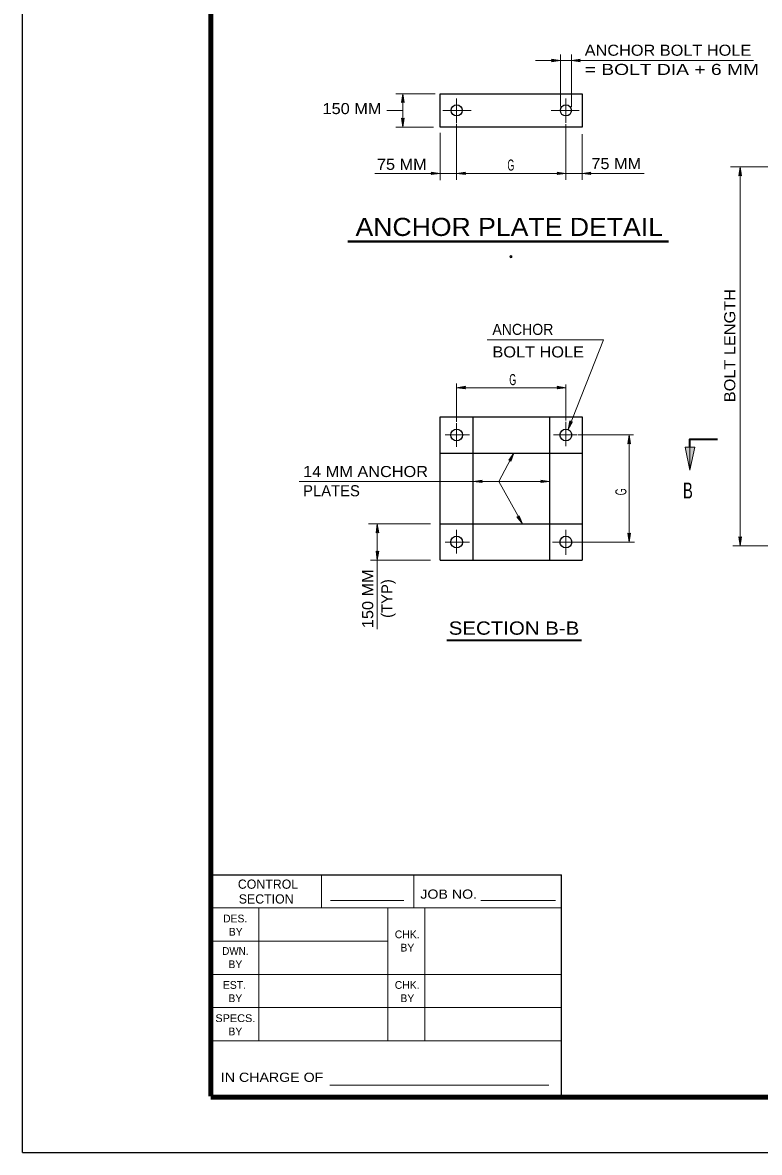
# Model space of a CAD drawing. Extents: x 312601.859 to 312602.7, y 144420.109 to 144420.704.
# Drawn here: x 312601.8593 to 312602.0589, y 144420.1095 to 144420.4155 of the extents above; entities that cross this region are included whole.
import ezdxf
from ezdxf.enums import TextEntityAlignment as Align

# ---------------------------------------------------------------- set-up
doc = ezdxf.new("R2010")
doc.units = 0
doc.header["$LTSCALE"] = 0.0012
doc.header["$PDMODE"] = 32
doc.header["$PDSIZE"] = 0.0006
doc.linetypes.add('DOT_DASHED', pattern=[7.7, 5, -1.2, 0.3, -1.2])
doc.linetypes.add('LONG_DASHED', pattern=[7.5, 6, -1.5])
for name, color, linetype, lineweight in [('1', 7, 'Continuous', 13), ('2', 7, 'Continuous', 13), ('39', 7, 'Continuous', 13)]:
    doc.layers.add(name, color=color, linetype=linetype, lineweight=lineweight)

msp = doc.modelspace()

# ---------------------------------------------------------------- hatches: boundary and pattern name
at = {"layer": '1'}
for points in [[(312602.0388, 144420.3005), (312602.0401, 144420.3005), (312602.0401, 144420.2943)], [(312602.0414, 144420.3005), (312602.0401, 144420.3005), (312602.0401, 144420.2943)]]:
    msp.add_hatch(color=256, dxfattribs=at).paths.add_polyline_path(points)
at = {"layer": '39'}
for points in [[(312602.0028, 144420.4052), (312602.0026, 144420.4056), (312602.005, 144420.4052), (312602.0026, 144420.4049)], [(312602.0102, 144420.4052), (312602.0104, 144420.4049), (312602.008, 144420.4052), (312602.0104, 144420.4056)], [(312601.9623, 144420.394), (312601.962, 144420.3938), (312601.9623, 144420.3962), (312601.9627, 144420.3938)], [(312601.9623, 144420.3894), (312601.9627, 144420.3896), (312601.9623, 144420.3872), (312601.962, 144420.3896)], [(312602.0537, 144420.3742), (312602.0534, 144420.374), (312602.0537, 144420.3764), (312602.0541, 144420.374)], [(312601.9702, 144420.3746), (312601.97, 144420.375), (312601.9724, 144420.3746), (312601.97, 144420.3743)], [(312601.9791, 144420.3746), (312601.9793, 144420.3743), (312601.9769, 144420.3746), (312601.9793, 144420.375)], [(312602.0043, 144420.3746), (312602.0041, 144420.375), (312602.0065, 144420.3746), (312602.0041, 144420.3743)], [(312602.0131, 144420.3746), (312602.0133, 144420.3743), (312602.0109, 144420.3746), (312602.0133, 144420.375)], [(312601.9791, 144420.3166), (312601.9793, 144420.3163), (312601.9769, 144420.3166), (312601.9793, 144420.317)], [(312602.0043, 144420.3166), (312602.0041, 144420.317), (312602.0065, 144420.3166), (312602.0041, 144420.3163)], [(312602.0079, 144420.3073), (312602.0083, 144420.3074), (312602.0071, 144420.3053), (312602.0076, 144420.3076)], [(312602.0236, 144420.3016), (312602.0233, 144420.3014), (312602.0236, 144420.3038), (312602.024, 144420.3014)], [(312601.9914, 144420.297), (312601.991, 144420.297), (312601.9924, 144420.2989), (312601.9916, 144420.2966)], [(312601.9836, 144420.2912), (312601.9838, 144420.2909), (312601.9814, 144420.2912), (312601.9838, 144420.2916)], [(312601.9999, 144420.2912), (312601.9997, 144420.2916), (312602.0021, 144420.2912), (312601.9997, 144420.2909)], [(312601.9936, 144420.2816), (312601.9938, 144420.2819), (312601.9947, 144420.2797), (312601.9932, 144420.2816)], [(312601.9554, 144420.2775), (312601.9551, 144420.2773), (312601.9554, 144420.2797), (312601.9558, 144420.2773)], [(312602.0236, 144420.277), (312602.024, 144420.2772), (312602.0236, 144420.2748), (312602.0233, 144420.2772)], [(312602.0537, 144420.276), (312602.0541, 144420.2762), (312602.0537, 144420.2738), (312602.0534, 144420.2762)], [(312601.9554, 144420.2721), (312601.9558, 144420.2723), (312601.9554, 144420.2699), (312601.9551, 144420.2723)]]:
    msp.add_hatch(color=256, dxfattribs=at).paths.add_polyline_path(points)

# ---------------------------------------------------------------- linework, layer by layer
at = {"layer": '1'}
for p, q in [((312602.005, 144420.4068), (312602.005, 144420.3928)), ((312602.008, 144420.4068), (312602.008, 144420.3927)), ((312601.9604, 144420.3962), (312601.9711, 144420.3962)), ((312601.9769, 144420.3881), (312601.9769, 144420.3729)), ((312602.0065, 144420.388), (312602.0065, 144420.3729)), ((312601.9706, 144420.3872), (312601.9604, 144420.3872)), ((312601.9623, 144420.3872), (312601.9623, 144420.3871)), ((312601.9724, 144420.3728), (312601.9724, 144420.3856)), ((312602.0109, 144420.3853), (312602.0109, 144420.3729)), ((312602.0511, 144420.3764), (312602.1223, 144420.3764)), ((312602.0537, 144420.3764), (312602.0537, 144420.2738)), ((312601.9547, 144420.3746), (312601.9724, 144420.3746)), ((312601.9724, 144420.3746), (312601.9769, 144420.3746)), ((312602.0109, 144420.3746), (312602.0277, 144420.3746)), ((312601.9852, 144420.3296), (312602.0167, 144420.3296)), ((312602.0071, 144420.3053), (312602.0167, 144420.3296)), ((312601.9769, 144420.3177), (312601.9769, 144420.3074)), ((312602.0065, 144420.3175), (312602.0065, 144420.3077)), ((312601.9769, 144420.3166), (312602.0065, 144420.3166)), ((312602.0097, 144420.3038), (312602.0248, 144420.3038)), ((312602.0236, 144420.3038), (312602.0236, 144420.2748)), ((312601.9883, 144420.2912), (312601.9924, 144420.2989)), ((312601.9883, 144420.2912), (312601.9947, 144420.2797)), ((312601.953, 144420.2797), (312601.9698, 144420.2797)), ((312602.0251, 144420.2748), (312602.0084, 144420.2748)), ((312602.0517, 144420.2738), (312602.1215, 144420.2738)), ((312601.9536, 144420.2699), (312601.9698, 144420.2699))]:
    msp.add_line(p, q, dxfattribs=at)
at = {"layer": '1', "lineweight": 25}
for p, q in [((312601.9724, 144420.3872), (312601.9724, 144420.3962)), ((312601.9724, 144420.3962), (312602.0109, 144420.3962)), ((312602.0109, 144420.3962), (312602.0109, 144420.3872)), ((312602.0109, 144420.3872), (312601.9724, 144420.3872)), ((312601.9724, 144420.3087), (312602.0109, 144420.3087)), ((312601.9724, 144420.2699), (312601.9724, 144420.3087)), ((312602.011, 144420.2699), (312602.011, 144420.3087)), ((312601.9814, 144420.2797), (312601.9814, 144420.2989)), ((312602.0021, 144420.2989), (312602.0021, 144420.2797)), ((312601.9724, 144420.2699), (312602.0109, 144420.2699))]:
    msp.add_line(p, q, dxfattribs=at)
at = {"layer": '1', "linetype": 'DOT_DASHED'}
for p, q in [((312601.9769, 144420.3949), (312601.9769, 144420.3883)), ((312602.0065, 144420.3949), (312602.0065, 144420.3883)), ((312601.9732, 144420.3917), (312601.9808, 144420.3917)), ((312602.0025, 144420.3917), (312602.0101, 144420.3917)), ((312601.9769, 144420.307), (312601.9769, 144420.3006)), ((312602.0065, 144420.3074), (312602.0065, 144420.3008)), ((312601.9738, 144420.3038), (312601.9804, 144420.3038)), ((312602.0031, 144420.3038), (312602.0095, 144420.3038)), ((312601.9769, 144420.2781), (312601.9769, 144420.2717)), ((312602.0065, 144420.2781), (312602.0065, 144420.2713)), ((312601.9738, 144420.2748), (312601.9804, 144420.2748)), ((312602.0029, 144420.2748), (312602.0099, 144420.2748))]:
    msp.add_line(p, q, dxfattribs=at)
at = {"layer": '1', "linetype": 'LONG_DASHED', "lineweight": 25}
for p, q in [((312601.9814, 144420.2989), (312601.9814, 144420.3087)), ((312602.0021, 144420.3087), (312602.0021, 144420.2989)), ((312601.9814, 144420.2699), (312601.9814, 144420.2797)), ((312602.0021, 144420.2797), (312602.0021, 144420.2699))]:
    msp.add_line(p, q, dxfattribs=at)
at = {"layer": '1'}
for points in [[(312601.9983, 144420.4052), (312602.005, 144420.4052), (312602.008, 144420.4052), (312602.0573, 144420.4052)], [(312601.9623, 144420.3963), (312601.9623, 144420.3962), (312601.9623, 144420.3872)], [(312601.9769, 144420.3746), (312602.0065, 144420.3746), (312602.0109, 144420.3746)], [(312601.9342, 144420.2912), (312601.9814, 144420.2912), (312602.0021, 144420.2912)], [(312601.9554, 144420.2797), (312601.9554, 144420.2699), (312601.9554, 144420.2512)]]:
    msp.add_lwpolyline(points, dxfattribs=at)
at = {"layer": '1', "lineweight": 35}
msp.add_lwpolyline([(312602.0401, 144420.3005), (312602.0401, 144420.3027), (312602.0476, 144420.3027)], dxfattribs=at)
at = {"layer": '1', "lineweight": 25}
for points in [[(312601.9724, 144420.2989), (312601.9814, 144420.2989), (312602.0021, 144420.2989), (312602.0109, 144420.2989)], [(312601.9724, 144420.2797), (312601.9814, 144420.2797), (312602.0021, 144420.2797), (312602.0109, 144420.2797)]]:
    msp.add_lwpolyline(points, dxfattribs=at)
at = {"layer": '1'}
for points in [[(312602.0388, 144420.3005), (312602.0401, 144420.3005), (312602.0401, 144420.2943)], [(312602.0414, 144420.3005), (312602.0401, 144420.3005), (312602.0401, 144420.2943)]]:
    msp.add_lwpolyline(points, close=True, dxfattribs=at)
at = {"layer": '1', "lineweight": 25}
for centre, radius in [((312601.9769, 144420.3917), 0.0015), ((312602.0065, 144420.3917), 0.0015), ((312601.9769, 144420.3038), 0.0016), ((312602.0065, 144420.3038), 0.0016), ((312601.9769, 144420.2748), 0.0016), ((312602.0065, 144420.2748), 0.0016)]:
    msp.add_circle(centre, radius, dxfattribs=at)
at = {"layer": '2'}
msp.add_line((312601.9623, 144420.3917), (312601.958, 144420.3917), dxfattribs=at)
at = {"layer": '2', "lineweight": 40}
msp.add_line((312602.0343, 144420.3562), (312601.9474, 144420.3562), dxfattribs=at)
at = {"layer": '2', "lineweight": 35}
msp.add_line((312601.9742, 144420.2482), (312602.0107, 144420.2482), dxfattribs=at)
at = {"layer": '2'}
msp.add_point((312601.9916, 144420.3521), dxfattribs=at)
at = {"layer": '39', "lineweight": 25}
for p, q in [((312601.8593, 144420.1095), (312601.8593, 144420.7035)), ((312601.9103, 144420.1847), (312602.0053, 144420.1847)), ((312602.0053, 144420.1247), (312602.0053, 144420.1847))]:
    msp.add_line(p, q, dxfattribs=at)
at = {"layer": '39'}
for p, q in [((312601.9103, 144420.1247), (312601.9103, 144420.1847)), ((312601.9403, 144420.1757), (312601.9403, 144420.1847)), ((312601.9653, 144420.1757), (312601.9653, 144420.1847)), ((312601.9427, 144420.1777), (312601.9626, 144420.1777)), ((312601.9835, 144420.1777), (312602.0037, 144420.1777)), ((312601.9103, 144420.1757), (312602.0053, 144420.1757)), ((312601.9233, 144420.1397), (312601.9233, 144420.1757)), ((312601.9583, 144420.1397), (312601.9583, 144420.1757)), ((312601.9683, 144420.1397), (312601.9683, 144420.1757)), ((312601.9103, 144420.1667), (312601.9583, 144420.1667)), ((312601.9103, 144420.1577), (312602.0053, 144420.1577)), ((312601.9103, 144420.1487), (312602.0053, 144420.1487)), ((312601.9103, 144420.1397), (312602.0053, 144420.1397)), ((312601.9425, 144420.1277), (312602.0019, 144420.1277)), ((312601.9103, 144420.1247), (312602.0053, 144420.1247))]:
    msp.add_line(p, q, dxfattribs=at)
at = {"layer": '39', "lineweight": 25}
msp.add_lwpolyline([(312601.8593, 144420.1095), (312602.7003, 144420.1095), (312602.7003, 144420.7035)], dxfattribs=at)
at = {"layer": '39', "lineweight": 158}
for points in [[(312601.9103, 144420.1245), (312602.6853, 144420.1245), (312602.6853, 144420.6645)], [(312601.9103, 144420.1247), (312601.9103, 144420.6645), (312602.6853, 144420.6645)]]:
    msp.add_lwpolyline(points, dxfattribs=at)
at = {"layer": '39'}
for points in [[(312602.0028, 144420.4052), (312602.0026, 144420.4056), (312602.005, 144420.4052), (312602.0026, 144420.4049)], [(312602.0102, 144420.4052), (312602.0104, 144420.4049), (312602.008, 144420.4052), (312602.0104, 144420.4056)], [(312601.9623, 144420.394), (312601.962, 144420.3938), (312601.9623, 144420.3962), (312601.9627, 144420.3938)], [(312601.9623, 144420.3894), (312601.9627, 144420.3896), (312601.9623, 144420.3872), (312601.962, 144420.3896)], [(312602.0537, 144420.3742), (312602.0534, 144420.374), (312602.0537, 144420.3764), (312602.0541, 144420.374)], [(312601.9702, 144420.3746), (312601.97, 144420.375), (312601.9724, 144420.3746), (312601.97, 144420.3743)], [(312601.9791, 144420.3746), (312601.9793, 144420.3743), (312601.9769, 144420.3746), (312601.9793, 144420.375)], [(312602.0043, 144420.3746), (312602.0041, 144420.375), (312602.0065, 144420.3746), (312602.0041, 144420.3743)], [(312602.0131, 144420.3746), (312602.0133, 144420.3743), (312602.0109, 144420.3746), (312602.0133, 144420.375)], [(312601.9791, 144420.3166), (312601.9793, 144420.3163), (312601.9769, 144420.3166), (312601.9793, 144420.317)], [(312602.0043, 144420.3166), (312602.0041, 144420.317), (312602.0065, 144420.3166), (312602.0041, 144420.3163)], [(312602.0079, 144420.3073), (312602.0083, 144420.3074), (312602.0071, 144420.3053), (312602.0076, 144420.3076)], [(312602.0236, 144420.3016), (312602.0233, 144420.3014), (312602.0236, 144420.3038), (312602.024, 144420.3014)], [(312601.9914, 144420.297), (312601.991, 144420.297), (312601.9924, 144420.2989), (312601.9916, 144420.2966)], [(312601.9836, 144420.2912), (312601.9838, 144420.2909), (312601.9814, 144420.2912), (312601.9838, 144420.2916)], [(312601.9999, 144420.2912), (312601.9997, 144420.2916), (312602.0021, 144420.2912), (312601.9997, 144420.2909)], [(312601.9936, 144420.2816), (312601.9938, 144420.2819), (312601.9947, 144420.2797), (312601.9932, 144420.2816)], [(312601.9554, 144420.2775), (312601.9551, 144420.2773), (312601.9554, 144420.2797), (312601.9558, 144420.2773)], [(312602.0236, 144420.277), (312602.024, 144420.2772), (312602.0236, 144420.2748), (312602.0233, 144420.2772)], [(312602.0537, 144420.276), (312602.0541, 144420.2762), (312602.0537, 144420.2738), (312602.0534, 144420.2762)], [(312601.9554, 144420.2721), (312601.9558, 144420.2723), (312601.9554, 144420.2699), (312601.9551, 144420.2723)]]:
    msp.add_lwpolyline(points, close=True, dxfattribs=at)

# ---------------------------------------------------------------- texts
at = {"layer": '1'}
for s, height, p in [('CONTROL', 0.0025, (312601.9258, 144420.1809)), ('SECTION', 0.0025, (312601.9253, 144420.1769)), ('DES.', 0.0021, (312601.9169, 144420.1718)), ('BY', 0.0021, (312601.91705, 144420.1682)), ('CHK.', 0.0021, (312601.9635, 144420.1675)), ('BY', 0.0021, (312601.96355, 144420.1639)), ('BY', 0.0021, (312601.91695, 144420.1594)), ('EST.', 0.0021, (312601.9167, 144420.1538)), ('CHK.', 0.0021, (312601.9635, 144420.1538)), ('BY', 0.0021, (312601.91695, 144420.1502)), ('BY', 0.0021, (312601.96355, 144420.1502)), ('BY', 0.0021, (312601.91695, 144420.1412))]:
    msp.add_text(s, height=height, dxfattribs=at).set_placement(p, align=Align.CENTER)
for s, height, width, p in [('JOB NO.', 0.0025, 1.15, (312601.97475, 144420.1782)), ('DWN.', 0.0021, 0.95, (312601.91695, 144420.163)), ('SPECS.', 0.0021, 1.05, (312601.91695, 144420.1448)), ('IN CHARGE OF', 0.0025, 1.15, (312601.9269, 144420.1286))]:
    msp.add_text(s, height=height, dxfattribs=dict(at, width=width)).set_placement(p, align=Align.CENTER)
at = {"layer": '2'}
for s, width, p in [('ANCHOR BOLT HOLE', 1.1, (312602.0116, 144420.4065)), ('= BOLT DIA + 6 MM', 1.3, (312602.0116, 144420.4013)), ('14 MM ANCHOR', 1.1, (312601.9353, 144420.2924))]:
    msp.add_text(s, height=0.003, dxfattribs=dict(at, width=width)).set_placement(p)
for s, height, width, p in [('150 MM', 0.003, 1.1, (312601.94855, 144420.3907)), ('75 MM', 0.003, 1.1, (312601.96205, 144420.3756)), ('G', 0.003, 0.6, (312601.9916, 144420.3754)), ('75 MM', 0.003, 1.1, (312602.02015, 144420.3758)), ('ANCHOR PLATE DETAIL', 0.0049, 1.1, (312601.99115, 144420.3577)), ('ANCHOR', 0.003, 0.95, (312601.99485, 144420.3309)), ('BOLT HOLE', 0.003, 1.1, (312601.999, 144420.3248)), ('G', 0.003, 0.6, (312601.9921, 144420.3173)), ('B', 0.0043, 0.7, (312602.03955, 144420.2866)), ('SECTION B-B', 0.0036, 1.15, (312601.99245, 144420.2497))]:
    msp.add_text(s, height=height, dxfattribs=dict(at, width=width)).set_placement(p, align=Align.CENTER)
for s, height, width, p in [('BOLT LENGTH', 0.002999, 1.1, (312602.0524, 144420.328)), ('G', 0.003, 0.6, (312602.0229, 144420.2884)), ('150 MM', 0.003, 1.1, (312601.9543, 144420.25945))]:
    msp.add_text(s, height=height, rotation=90, dxfattribs=dict(at, width=width)).set_placement(p, align=Align.CENTER)
msp.add_text('PLATES', height=0.003, dxfattribs=at).set_placement((312601.9353, 144420.2872))
msp.add_text('(TYP)', height=0.003, rotation=90, dxfattribs=at).set_placement((312601.9595, 144420.2595), align=Align.CENTER)

doc.saveas('drawing.dxf')
